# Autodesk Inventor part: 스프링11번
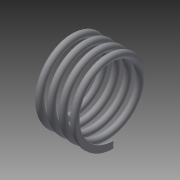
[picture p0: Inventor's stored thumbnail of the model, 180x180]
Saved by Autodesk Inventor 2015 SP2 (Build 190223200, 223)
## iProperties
Created: 2015-06
Part Number: 스프링11번
Material: 일반
Document SubType Name: Modeling
Designer: AMC
Density: 1 g/cm^3
Appearance: 기본값
Author: AMC
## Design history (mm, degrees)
sketch "스케치1"
  geometry: L1 (0, 0)-(0, -8); L2 (0, 0)-(10.5, 0); C1 r 0.75 at (0, -8)
  constraints: 4 end point, 1 centre point, 1 coincident, 1 horizontal, 1 vertical
  dimensions: "d0" = 8 distance of L1.start L1.end; "d1" = 1.5 diameter of C1; "d2" = 10.5 distance of L1.start L2.end (derived)
feature "코일1" sketch "스케치1" pitch "d3" = 10; turns "d5" = 4; dims "d4" = 10.5 (= d2), "d6" = 0, angle "d7" = 90 deg, angle "d8" = 90 deg, "d9" = 0, "d10" = 0
sketch "스케치2"
  geometry: L1 (0, -21.66)-(6.113, -21.66); L2 (6.113, -21.66)-(6.113, 4.55); L3 (6.113, 4.55)-(0, 4.55); L4 (0, 4.55)-(0, -21.66); L5 (-10.5, 3.586)-(-20.148, 3.586); L6 (-20.148, 3.586)-(-20.148, -23.831); L7 (-20.148, -23.831)-(-10.5, -23.831); L8 (-10.5, -23.831)-(-10.5, 3.586); 1 further point
  constraints: 16 end point, 4 parallel, 2 horizontal, 2 perpendicular, 1 point on line
  dimensions: "d11" = 10.5 distance between parallel lines of L4 L8 (= d2)
extrude "돌출1" cut sketch "스케치2" stored distance "d12" = 50; taper "d13" = 0 deg
node "솔리드1"
